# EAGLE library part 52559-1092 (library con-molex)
FFC/FPC-to-Board 0.50mm (.020") SMT, Vertical, ZIF Receptacle Source: http://www.molex.com/product/ffc/52559.html
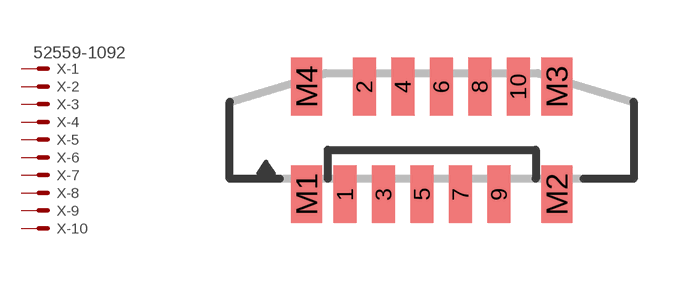
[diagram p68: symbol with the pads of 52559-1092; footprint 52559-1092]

Designator prefix X; gates -1=MV -2=M -3=M -4=M -5=M -6=M -7=M -8=M -9=M -10=M

## 52559-1092 (MPN: 52559-1092; OC_FARNELL: unknown; OC_NEWARK: 92M6172)  [52559-1092]
1  -1:S  pas
2  -2:S  pas
3  -3:S  pas
4  -4:S  pas
5  -5:S  pas
6  -6:S  pas
7  -7:S  pas
8  -8:S  pas
9  -9:S  pas
10  -10:S  pas

## Footprint 52559-1092 (pad centres in mm)
FFC/FPC-to-Board 0.50mm (.020") SMT, Vertical, ZIF Receptacle Source: http://www.molex.com/product/ffc/52559.html
smd 0.6 x 1.5: 1 -2.25,-1.4; 2 -1.75,1.4; 3 -1.25,-1.4; 4 -0.75,1.4; 5 -0.25,-1.4; 6 0.25,1.4; 7 0.75,-1.4; 8 1.25,1.4; 9 1.75,-1.4; 10 2.25,1.4
smd 0.8 x 1.5: M1 -3.25,-1.4; M2 3.25,-1.4; M3 3.25,1.4; M4 -3.25,1.4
